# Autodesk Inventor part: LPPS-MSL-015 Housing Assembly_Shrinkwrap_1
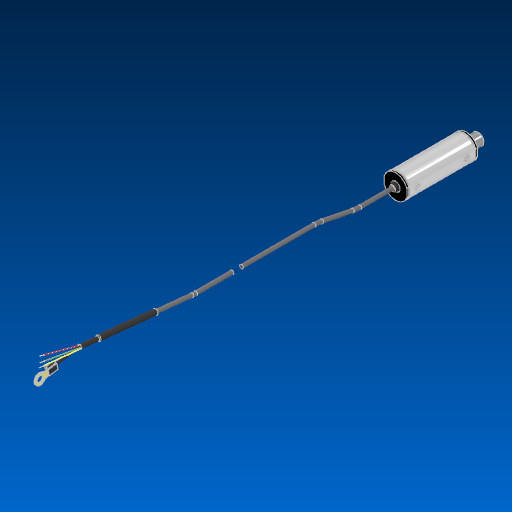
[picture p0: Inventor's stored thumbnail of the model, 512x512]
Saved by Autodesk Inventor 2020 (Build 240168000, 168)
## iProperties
Created: 2019-08
Part Number: LPPS-MSL-015 Housing Assembly_Shrinkwrap_1
Material: Generic
Document SubType Name: Modeling
Designer: J. Nielson
Density: 1 g/cm^3
Appearance: Default
Author: J. Nielson
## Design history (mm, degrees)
node "Assembly1"
body "Solid1"
node "Part1:1"
node "Part2:1"
body "Solid2"
node "Part3:1"
body "Solid3"
node "Part4:1"
body "Solid4"
node "Part5:1"
body "Solid5"
node "Part6:1"
body "Solid6"
node "Part7:1"
body "Solid7"
node "Part8:1"
body "Solid8"
node "Part9:1"
body "Solid9"
node "Part10:1"
body "Solid10"
node "Part11:1"
body "Solid11"
node "Part12:1"
body "Solid12"
node "Part13:1"
body "Solid13"
node "Part14:1"
body "Solid14"
node "Part15:1"
body "Solid15"
node "Part16:1"
body "Solid16"
node "Part16:2"
body "Solid17"
node "Part17:1"
body "Solid18"
node "Part17:2"
body "Solid19"
